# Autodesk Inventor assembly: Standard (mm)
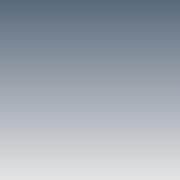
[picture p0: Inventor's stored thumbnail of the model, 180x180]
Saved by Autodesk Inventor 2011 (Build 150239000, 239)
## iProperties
Shininess: 64.0
Length Units: 11269
Angle Units: 11279
Time Units: 11290
Mass Units: 11283
Length Display Precision: 3
Angle Display Precision: 2
Compacted: True
Created: 2002-07
Part Number: Standard (mm)
Document SubType Name: Assembly
Density: 0.0
Volumn: 0.0
Area: 0.0
PropertySet Name: Model Information
Control State: 0
Master: False
Checked Out: False
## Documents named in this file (1)
- M:\Programs\AUT_Inventor2011EN\Templates\CC\Standard.iam
